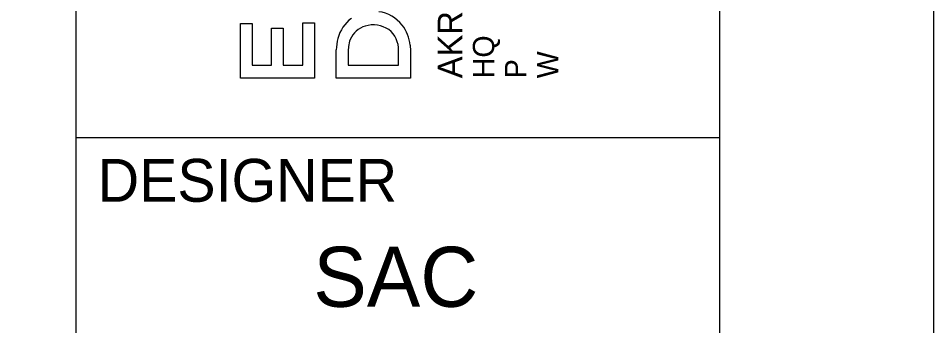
# Model space of a CAD drawing. Extents: x -0.2 to 34, y 0 to 22.
# Drawn here: x 31.865 to 34, y 2.061 to 2.778 of the extents above; entities that cross this region are included whole.
import ezdxf

# ---------------------------------------------------------------- set-up
doc = ezdxf.new("R2010")
doc.units = 0
for name, color, linetype in [('SH_Border', 7, 'Continuous'), ('SH_Data', 7, 'Continuous'), ('SH_Named_Boundary', 7, 'Continuous')]:
    doc.layers.add(name, color=color, linetype=linetype)

msp = doc.modelspace()

# ---------------------------------------------------------------- linework, layer by layer
at = {"layer": 'SH_Border'}
for p, q in [((32, 0.5), (32, 21.5)), ((32, 2.5), (33.5, 2.5))]:
    msp.add_line(p, q, dxfattribs=at)
msp.add_lwpolyline([(1.5, 21.5), (33.5, 21.5), (33.5, 0.5), (1.5, 0.5)], close=True, dxfattribs=at)
at = {"layer": 'SH_Data'}
msp.add_lwpolyline([(0, 0), (34, 0), (34, 22), (0, 22)], close=True, dxfattribs=at)
at = {"layer": 'SH_Named_Boundary'}
for p, q in [((32.383, 2.6379), (32.383, 2.766)), ((32.383, 2.766), (32.4101, 2.766)), ((32.4101, 2.766), (32.4101, 2.6683)), ((32.455, 2.6683), (32.455, 2.7549)), ((32.455, 2.7549), (32.4822, 2.7549)), ((32.4822, 2.7549), (32.4822, 2.6683)), ((32.5286, 2.6683), (32.5286, 2.7672)), ((32.5286, 2.7672), (32.5557, 2.7672)), ((32.5557, 2.7672), (32.5557, 2.6379)), ((32.7785, 2.715), (32.7792, 2.7021)), ((32.6064, 2.638), (32.6064, 2.704)), ((32.6347, 2.7118), (32.6341, 2.7023)), ((32.6341, 2.7023), (32.6341, 2.6684)), ((32.7515, 2.6683), (32.7515, 2.7024)), ((32.7792, 2.7021), (32.7792, 2.638)), ((32.4101, 2.6683), (32.455, 2.6683)), ((32.4822, 2.6683), (32.5286, 2.6683)), ((32.6341, 2.6684), (32.7515, 2.6683)), ((32.5557, 2.6379), (32.383, 2.6379)), ((32.7792, 2.638), (32.6064, 2.638))]:
    msp.add_line(p, q, dxfattribs=at)
msp.add_lwpolyline([(32.383, 2.6379), (32.383, 2.766), (32.4101, 2.766), (32.4101, 2.6683), (32.455, 2.6683), (32.455, 2.7549), (32.4822, 2.7549), (32.4822, 2.6683), (32.5286, 2.6683), (32.5286, 2.7672), (32.5557, 2.7672), (32.5557, 2.6379)], close=True, dxfattribs=at)
for points in [[(32.7785, 2.715), (32.7792, 2.7021), (32.7792, 2.638), (32.6064, 2.638)], [(32.6064, 2.638), (32.6064, 2.704)], [(32.6347, 2.7118), (32.6341, 2.7023), (32.6341, 2.6684), (32.7515, 2.6683), (32.7515, 2.7024)]]:
    msp.add_lwpolyline(points, dxfattribs=at)
for centre, radius, start, end in [((32.6939, 2.7089), 0.0865, 127.2362, 165.148), ((32.6939, 2.7089), 0.0865, 127.2362, 165.148), ((32.6946, 2.7113), 0.0827, 37.8521, 82.402), ((32.6946, 2.7113), 0.0827, 37.8521, 82.402), ((32.6889, 2.7078), 0.054, 106.1881, 157.3861), ((32.6889, 2.7078), 0.054, 106.1881, 157.3861), ((32.6928, 2.6986), 0.0639, 55.6727, 107.2093), ((32.6928, 2.6986), 0.0639, 55.6727, 107.2093), ((32.6859, 2.7057), 0.0931, 5.7333, 37.304), ((32.6859, 2.7057), 0.0931, 5.7333, 37.304), ((32.6929, 2.705), 0.0587, 357.4662, 52.2665), ((32.6929, 2.705), 0.0587, 357.4662, 52.2665), ((32.7143, 2.7028), 0.1078, 164.7861, 179.3704), ((32.7143, 2.7028), 0.1078, 164.7861, 179.3704), ((32.6983, 2.7039), 0.0641, 157.3571, 172.9275), ((32.6983, 2.7039), 0.0641, 157.3571, 172.9275)]:
    msp.add_arc(centre, radius, start, end, dxfattribs=at)

# ---------------------------------------------------------------- texts
for s, height, p in [('AKRON / CLEVELAND / COLUMBUS', 0.056969, (32.9001, 2.638)), ('HQ ', 0.04985, (32.9749, 2.638)), ('W', 0.0498, (33.1244, 2.638)), ('P', 0.0498, (33.0497, 2.638))]:
    msp.add_text(s, height=height, rotation=90, dxfattribs=at).set_placement(p)
for s, height, p in [('DESIGNER', 0.1, (32.05, 2.35)), ('SAC', 0.14, (32.5528, 2.105))]:
    msp.add_text(s, height=height, dxfattribs=at).set_placement(p)

doc.saveas('drawing.dxf')
